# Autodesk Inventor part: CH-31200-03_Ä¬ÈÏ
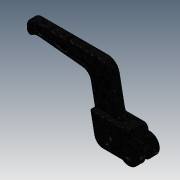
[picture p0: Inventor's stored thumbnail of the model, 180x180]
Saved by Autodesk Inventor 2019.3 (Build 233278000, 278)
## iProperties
Created: 2010-06
Part Number: CH-31200-03_Ä¬ÈÏ
Material: Ogólny
Document SubType Name: Modeling
Designer: CADENGINEERING4
Density: 1 g/cm^3
Appearance: Czarny
Author: CADENGINEERING4
Revision Number: ÈÎºÎ
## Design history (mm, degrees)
feature "NONE"
node "Bryła1"
